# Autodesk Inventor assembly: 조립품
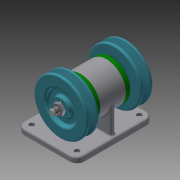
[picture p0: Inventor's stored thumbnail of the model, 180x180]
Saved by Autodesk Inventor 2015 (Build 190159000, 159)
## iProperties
Created: 2019-09
Part Number: 조립품
Document SubType Name: Assembly
Designer: now
Author: now
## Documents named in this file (10)
- C:\Users\now\Desktop\490904V1035\조립품.iam
- C:\Users\now\Desktop\490904V1035\V-벨트풀리.ipt
- C:\Users\now\Desktop\490904V1035\너트 M10x1.ipt
- C:\Users\now\Desktop\490904V1035\베어링 6004.ipt
- C:\Users\now\Desktop\490904V1035\본체.ipt
- C:\Users\now\Desktop\490904V1035\볼트 M4.ipt
- C:\Users\now\Desktop\490904V1035\오일 실 17 30 5.ipt
- C:\Users\now\Desktop\490904V1035\축.ipt
- C:\Users\now\Desktop\490904V1035\커버.ipt
- C:\Users\now\Desktop\490904V1035\키 5 x 5 x 12.ipt
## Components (2 placed, 1 different names)
1. V-벨트풀리:1 — 각도:3
2. V-벨트풀리:2 — 각도:4
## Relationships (2: Angle 2)
- 각도:3 [Angle]: V-벨트풀리:1
- 각도:4 [Angle]: V-벨트풀리:2
